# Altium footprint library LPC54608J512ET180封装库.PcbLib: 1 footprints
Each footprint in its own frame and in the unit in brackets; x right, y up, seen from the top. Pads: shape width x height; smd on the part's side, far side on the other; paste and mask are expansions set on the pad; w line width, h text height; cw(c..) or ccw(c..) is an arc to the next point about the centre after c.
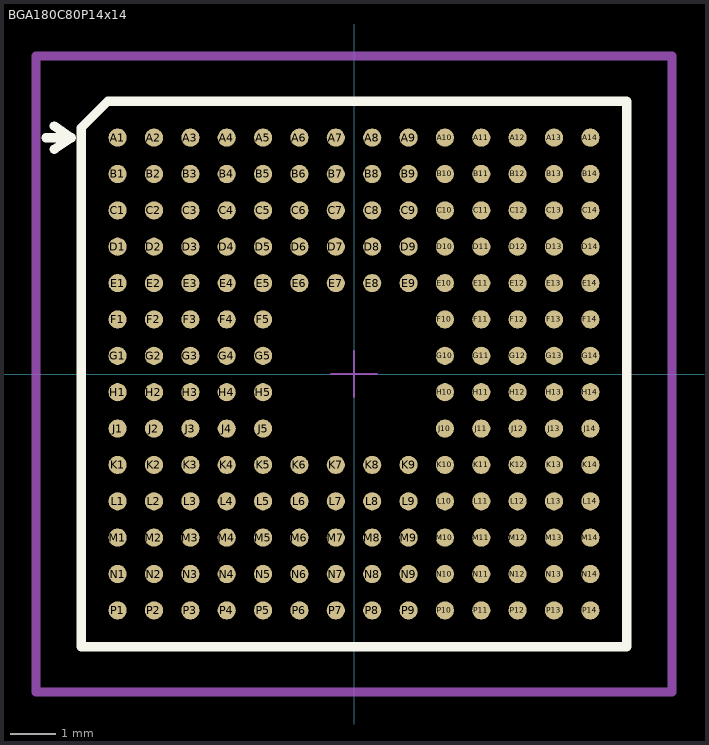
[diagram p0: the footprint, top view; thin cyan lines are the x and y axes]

## BGA180C80P14x14 [mm] "LPC313X"
height 2.8
pads (180):
  round 0.4 smd: A1(-5.2,5.2) A2(-4.4,5.2) A3(-3.6,5.2) A4(-2.8,5.2) A5(-2,5.2) A6(-1.2,5.2) A7(-0.4,5.2) A8(0.4,5.2) A9(1.2,5.2) A10(2,5.2) A11(2.8,5.2) A12(3.6,5.2) A13(4.4,5.2) A14(5.2,5.2) B1(-5.2,4.4) B2(-4.4,4.4) B3(-3.6,4.4) B4(-2.8,4.4) B5(-2,4.4) B6(-1.2,4.4) B7(-0.4,4.4) B8(0.4,4.4) B9(1.2,4.4) B10(2,4.4) B11(2.8,4.4) B12(3.6,4.4) B13(4.4,4.4) B14(5.2,4.4) C1(-5.2,3.6) C2(-4.4,3.6) C3(-3.6,3.6) C4(-2.8,3.6) C5(-2,3.6) C6(-1.2,3.6) C7(-0.4,3.6) C8(0.4,3.6) C9(1.2,3.6) C10(2,3.6) C11(2.8,3.6) C12(3.6,3.6) C13(4.4,3.6) C14(5.2,3.6) D1(-5.2,2.8) D2(-4.4,2.8) D3(-3.6,2.8) D4(-2.8,2.8) D5(-2,2.8) D6(-1.2,2.8) D7(-0.4,2.8) D8(0.4,2.8) D9(1.2,2.8) D10(2,2.8) D11(2.8,2.8) D12(3.6,2.8) D13(4.4,2.8) D14(5.2,2.8) E1(-5.2,2) E2(-4.4,2) E3(-3.6,2) E4(-2.8,2) E5(-2,2) E6(-1.2,2) E7(-0.4,2) E8(0.4,2) E9(1.2,2) E10(2,2) E11(2.8,2) E12(3.6,2) E13(4.4,2) E14(5.2,2) F1(-5.2,1.2) F2(-4.4,1.2) F3(-3.6,1.2) F4(-2.8,1.2) F5(-2,1.2) F10(2,1.2) F11(2.8,1.2) F12(3.6,1.2) F13(4.4,1.2) F14(5.2,1.2) G1(-5.2,0.4) G2(-4.4,0.4) G3(-3.6,0.4) G4(-2.8,0.4) G5(-2,0.4) G10(2,0.4) G11(2.8,0.4) G12(3.6,0.4) G13(4.4,0.4) G14(5.2,0.4) H1(-5.2,-0.4) H2(-4.4,-0.4) H3(-3.6,-0.4) H4(-2.8,-0.4) H5(-2,-0.4) H10(2,-0.4) H11(2.8,-0.4) H12(3.6,-0.4) H13(4.4,-0.4) H14(5.2,-0.4) J1(-5.2,-1.2) J2(-4.4,-1.2) J3(-3.6,-1.2) J4(-2.8,-1.2) J5(-2,-1.2) J10(2,-1.2) J11(2.8,-1.2) J12(3.6,-1.2) J13(4.4,-1.2) J14(5.2,-1.2) K1(-5.2,-2) K2(-4.4,-2) K3(-3.6,-2) K4(-2.8,-2) K5(-2,-2) K6(-1.2,-2) K7(-0.4,-2) K8(0.4,-2) K9(1.2,-2) K10(2,-2) K11(2.8,-2) K12(3.6,-2) K13(4.4,-2) K14(5.2,-2) L1(-5.2,-2.8) L2(-4.4,-2.8) L3(-3.6,-2.8) L4(-2.8,-2.8) L5(-2,-2.8) L6(-1.2,-2.8) L7(-0.4,-2.8) L8(0.4,-2.8) L9(1.2,-2.8) L10(2,-2.8) L11(2.8,-2.8) L12(3.6,-2.8) L13(4.4,-2.8) L14(5.2,-2.8) M1(-5.2,-3.6) M2(-4.4,-3.6) M3(-3.6,-3.6) M4(-2.8,-3.6) M5(-2,-3.6) M6(-1.2,-3.6) M7(-0.4,-3.6) M8(0.4,-3.6) M9(1.2,-3.6) M10(2,-3.6) M11(2.8,-3.6) M12(3.6,-3.6) M13(4.4,-3.6) M14(5.2,-3.6) N1(-5.2,-4.4) N2(-4.4,-4.4) N3(-3.6,-4.4) N4(-2.8,-4.4) N5(-2,-4.4) N6(-1.2,-4.4) N7(-0.4,-4.4) N8(0.4,-4.4) N9(1.2,-4.4) N10(2,-4.4) N11(2.8,-4.4) N12(3.6,-4.4) N13(4.4,-4.4) N14(5.2,-4.4) P1(-5.2,-5.2) P2(-4.4,-5.2) P3(-3.6,-5.2) P4(-2.8,-5.2) P5(-2,-5.2) P6(-1.2,-5.2) P7(-0.4,-5.2) P8(0.4,-5.2) P9(1.2,-5.2) P10(2,-5.2) P11(2.8,-5.2) P12(3.6,-5.2) P13(4.4,-5.2) P14(5.2,-5.2)
Top Overlay:
  lines w0.2: -6,-6 -6,5.416 -5.416,6 6,6 6,-6 -6,-6
  lines w0.203: -6.775,5.2 -6.216,5.2 ; -6.597,4.946 -6.216,5.2 ; -6.597,5.454 -6.216,5.2
Mechanical 15:
  lines w0.05: -0.5,0 0.5,0 ; 0,-0.5 0,0.5
  lines w0.2: -7,-7 -7,7 7,7 7,-7 -7,-7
